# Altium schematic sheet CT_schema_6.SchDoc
size 278 x 170 mm
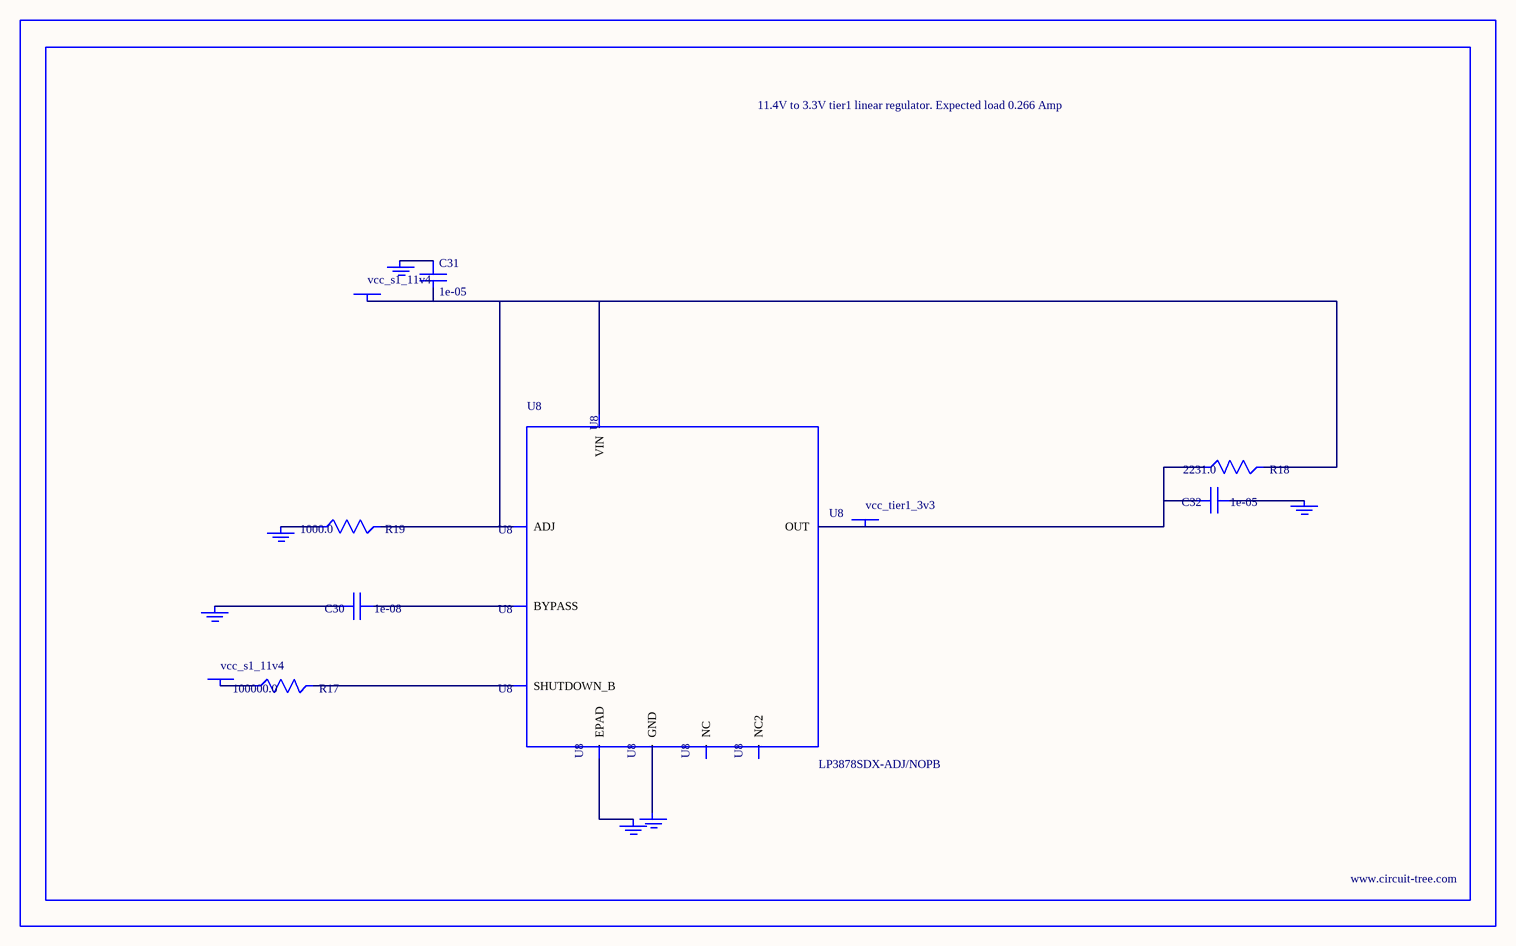
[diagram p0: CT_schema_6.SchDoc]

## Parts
BORDER5  (no value)
C30  1e-08  [C0402]
C31  1e-05  [C1210]
C32  1e-05  [C1210]
GND_INSTANCE_5_0  (no value)
GND_INSTANCE_5_1  (no value)
GND_INSTANCE_5_2  (no value)
GND_INSTANCE_5_3  (no value)
GND_INSTANCE_5_4  (no value)
GND_INSTANCE_5_5  (no value)
POWER_INSTANCE_5_0  vcc_s1_11v4
POWER_INSTANCE_5_1  vcc_s1_11v4
POWER_INSTANCE_5_2  vcc_tier1_3v3
R17  100000.0  [R0603]
R18  2231.0  [R0603]
R19  1000.0  [R0603]
U8  LP3878SDX-ADJ/NOPB  [WSON-8]

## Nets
NetC30_1: C30.1 U8.1(BYPASS)
NetC30_2: C30.2 GND_INSTANCE_5_0.0(GND)
NetC31_1: C31.1 GND_INSTANCE_5_1.0(GND)
NetC31_2: C31.2 POWER_INSTANCE_5_0.0(PWR) R18.2 R19.2 U8.4(VIN) U8.6(ADJ)
NetC32_1: C32.1 GND_INSTANCE_5_2.0(GND)
NetC32_2: C32.2 POWER_INSTANCE_5_2.0(PWR) R18.1 U8.5(OUT)
NetGND_INSTANCE_5_3_0: GND_INSTANCE_5_3.0(GND) R19.1
NetGND_INSTANCE_5_4_0: GND_INSTANCE_5_4.0(GND) U8.PAD(EPAD)
NetGND_INSTANCE_5_5_0: GND_INSTANCE_5_5.0(GND) U8.3(GND)
NetPOWER_INSTANCE_5_1_0: POWER_INSTANCE_5_1.0(PWR) R17.1
NetR17_2: R17.2 U8.8(SHUTDOWN_B)

Not connected (* = marked no-connect by the designer): U8 2(NC) 7(NC2)

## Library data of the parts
BORDER5 = BORDER_PAGE5
C30 = C0402C103K3RAC
C31 = C1210C106K5PACTU
C32 = GRM32DR61E106MA12L
GND_INSTANCE_5_0-GND_INSTANCE_5_5 = GND
POWER_INSTANCE_5_0-POWER_INSTANCE_5_2 = PWR
R17 = RC0603JR-07100KL
R18 = R18
R19 = RC0603JR-071KL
